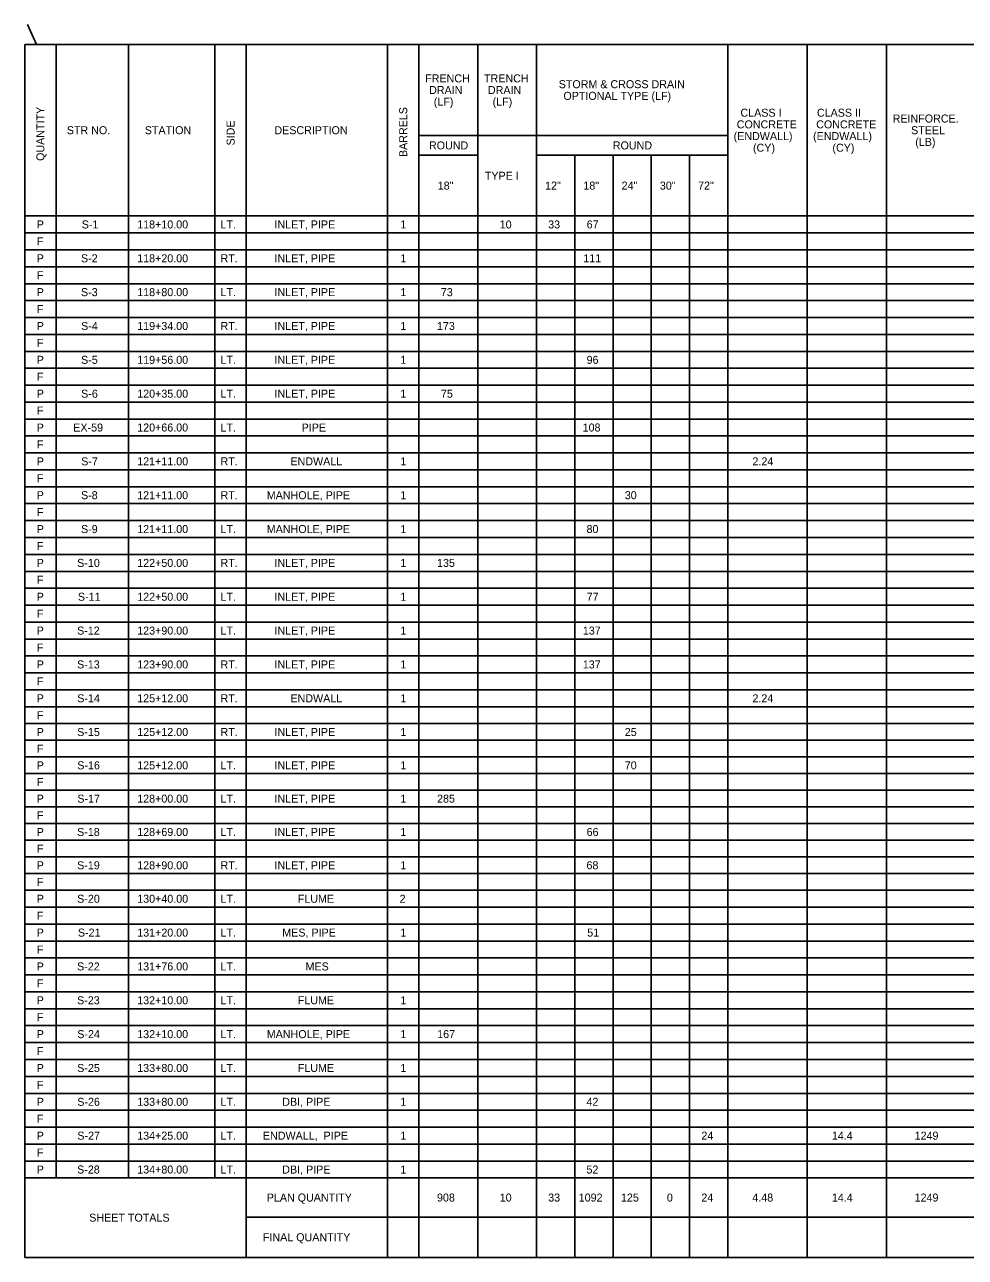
# Model space of a CAD drawing. Extents: x 0 to 765, y -1227 to 479.
# Drawn here: x 0.3 to 360, y 7 to 478.6 of the extents above; entities that cross this region are included whole.
import ezdxf

# ---------------------------------------------------------------- set-up
doc = ezdxf.new("R2010")
doc.units = 0
for name, color, linetype in [('Miscellaneous0', 7, 'Continuous'), ('PlotBorder_dp', 7, 'Continuous'), ('SheetLines_dp', 7, 'Continuous'), ('TextMinor', 7, 'Continuous'), ('TextShtNo', 7, 'Continuous')]:
    doc.layers.add(name, color=color, linetype=linetype)

msp = doc.modelspace()

# ---------------------------------------------------------------- linework, layer by layer
at = {"layer": 'PlotBorder_dp'}
for p, q in [((12.29, 471.05), (12.29, 37.35)), ((12.29, 471.05), (12.29, 37.35)), ((40.04, 471.05), (40.04, 37.35)), ((40.04, 471.05), (40.04, 37.35)), ((85.04, 471.05), (85.04, 6.97)), ((139.04, 471.05), (139.04, 6.97)), ((151.04, 471.05), (151.04, 6.97)), ((151.04, 471.05), (151.04, 6.97)), ((173.54, 471.05), (173.54, 6.97)), ((173.54, 471.05), (173.54, 6.97)), ((196.04, 471.05), (196.04, 6.97)), ((196.04, 471.05), (196.04, 6.97)), ((269.16, 471.05), (269.16, 6.97)), ((269.16, 471.05), (269.16, 6.97)), ((299.54, 471.05), (299.54, 405.42)), ((299.54, 471.05), (299.54, 6.97)), ((329.91, 471.05), (329.91, 405.42)), ((329.91, 471.05), (329.91, 6.97)), ((151.04, 436.17), (269.16, 436.17)), ((151.04, 428.67), (173.54, 428.67)), ((151.04, 428.67), (173.54, 428.67)), ((196.04, 428.67), (269.16, 428.67)), ((196.04, 428.67), (269.16, 428.67)), ((210.66, 428.67), (210.66, 6.97)), ((210.66, 428.67), (210.66, 6.97)), ((225.29, 428.67), (225.29, 6.97)), ((225.29, 428.67), (225.29, 6.97)), ((239.91, 428.67), (239.91, 6.97)), ((239.91, 428.67), (239.91, 6.97)), ((254.54, 428.67), (254.54, 22.35)), ((254.54, 428.67), (254.54, 6.97)), ((73.04, 405.42), (73.04, 37.35)), ((73.04, 405.42), (73.04, 37.35)), ((85.04, 405.42), (85.04, 6.97)), ((139.04, 405.42), (139.04, 398.95)), ((139.04, 147.42), (139.04, 6.97)), ((0.29, 37.35), (764.54, 37.35)), ((299.54, 37.35), (299.54, 6.97)), ((329.91, 37.35), (329.91, 6.97)), ((85.04, 22.35), (764.54, 22.35)), ((85.04, 22.35), (764.54, 22.35))]:
    msp.add_line(p, q, dxfattribs=at)
at = {"layer": 'SheetLines_dp'}
for p, q in [((0.29, 471.05), (764.54, 471.05)), ((0.29, 471.05), (0.29, 6.97)), ((73.04, 471.05), (73.04, 405.42)), ((0.29, 405.42), (764.54, 405.42)), ((0.29, 405.42), (764.54, 405.42)), ((0.29, 6.97), (764.54, 6.97))]:
    msp.add_line(p, q, dxfattribs=at)
at = {"layer": 'TextMinor'}
for p, q in [((0.29, 398.95), (764.54, 398.95)), ((40.04, 398.95), (85.04, 398.95)), ((0.29, 392.47), (764.54, 392.47)), ((0.29, 392.47), (764.54, 392.47)), ((0.29, 386), (764.54, 386)), ((12.29, 386), (764.54, 386)), ((0.29, 379.52), (764.54, 379.52)), ((0.29, 379.52), (764.54, 379.52)), ((0.29, 373.05), (764.54, 373.05)), ((12.29, 373.05), (764.54, 373.05)), ((0.29, 366.57), (764.54, 366.57)), ((0.29, 366.57), (764.54, 366.57)), ((0.29, 360.1), (764.54, 360.1)), ((12.29, 360.1), (764.54, 360.1)), ((0.29, 353.62), (764.54, 353.62)), ((0.29, 353.62), (764.54, 353.62)), ((0.29, 347.15), (764.54, 347.15)), ((12.29, 347.15), (764.54, 347.15)), ((0.29, 340.67), (764.54, 340.67)), ((0.29, 340.67), (764.54, 340.67)), ((0.29, 334.2), (764.54, 334.2)), ((12.29, 334.2), (764.54, 334.2)), ((0.29, 327.72), (764.54, 327.72)), ((0.29, 327.72), (764.54, 327.72)), ((0.29, 321.25), (764.54, 321.25)), ((12.29, 321.25), (764.54, 321.25)), ((0.29, 314.77), (764.54, 314.77)), ((0.29, 314.77), (764.54, 314.77)), ((0.29, 308.3), (764.54, 308.3)), ((12.29, 308.3), (764.54, 308.3)), ((0.29, 301.82), (764.54, 301.82)), ((0.29, 301.82), (764.54, 301.82)), ((0.29, 295.35), (764.54, 295.35)), ((12.29, 295.35), (764.54, 295.35)), ((0.29, 288.87), (764.54, 288.87)), ((0.29, 288.87), (764.54, 288.87)), ((0.29, 282.4), (764.54, 282.4)), ((12.29, 282.4), (764.54, 282.4)), ((0.29, 275.92), (764.54, 275.92)), ((0.29, 275.92), (764.54, 275.92)), ((0.29, 269.45), (764.54, 269.45)), ((12.29, 269.45), (764.54, 269.45)), ((0.29, 262.97), (764.54, 262.97)), ((0.29, 262.97), (764.54, 262.97)), ((0.29, 256.5), (764.54, 256.5)), ((12.29, 256.5), (764.54, 256.5)), ((0.29, 250.02), (764.54, 250.02)), ((0.29, 250.02), (764.54, 250.02)), ((0.29, 243.55), (764.54, 243.55)), ((12.29, 243.55), (764.54, 243.55)), ((0.29, 237.07), (764.54, 237.07)), ((0.29, 237.07), (764.54, 237.07)), ((0.29, 230.6), (764.54, 230.6)), ((12.29, 230.6), (764.54, 230.6)), ((0.29, 224.12), (764.54, 224.12)), ((0.29, 224.12), (764.54, 224.12)), ((0.29, 217.65), (764.54, 217.65)), ((12.29, 217.65), (764.54, 217.65)), ((0.29, 211.17), (764.54, 211.17)), ((0.29, 211.17), (764.54, 211.17)), ((0.29, 204.8), (764.54, 204.8)), ((12.29, 204.8), (764.54, 204.8)), ((0.29, 198.42), (764.54, 198.42)), ((0.29, 198.42), (764.54, 198.42)), ((0.29, 192.05), (764.54, 192.05)), ((12.29, 192.05), (764.54, 192.05)), ((0.29, 185.67), (764.54, 185.67)), ((0.29, 185.67), (764.54, 185.67)), ((0.29, 179.3), (764.54, 179.3)), ((12.29, 179.3), (764.54, 179.3)), ((0.29, 172.92), (764.54, 172.92)), ((0.29, 172.92), (764.54, 172.92)), ((0.29, 166.55), (764.54, 166.55)), ((12.29, 166.55), (764.54, 166.55)), ((0.29, 160.17), (764.54, 160.17)), ((0.29, 160.17), (764.54, 160.17)), ((0.29, 153.8), (764.54, 153.8)), ((12.29, 153.8), (764.54, 153.8)), ((0.29, 147.42), (764.54, 147.42)), ((0.29, 147.42), (764.54, 147.42)), ((0.29, 140.95), (764.54, 140.95)), ((0.29, 140.95), (764.54, 140.95)), ((0.29, 134.47), (764.54, 134.47)), ((0.29, 134.47), (764.54, 134.47)), ((0.29, 128), (764.54, 128)), ((0.29, 128), (764.54, 128)), ((0.29, 121.52), (764.54, 121.52)), ((0.29, 121.52), (764.54, 121.52)), ((0.29, 115.05), (764.54, 115.05)), ((0.29, 115.05), (764.54, 115.05)), ((0.29, 108.57), (764.54, 108.57)), ((0.29, 108.57), (764.54, 108.57)), ((0.29, 102.1), (764.54, 102.1)), ((0.29, 102.1), (764.54, 102.1)), ((0.29, 95.62), (764.54, 95.62)), ((0.29, 95.62), (764.54, 95.62)), ((0.29, 89.15), (764.54, 89.15)), ((0.29, 89.15), (764.54, 89.15)), ((0.29, 82.67), (764.54, 82.67)), ((0.29, 82.67), (764.54, 82.67)), ((0.29, 76.2), (764.54, 76.2)), ((0.29, 76.2), (764.54, 76.2)), ((0.29, 69.72), (764.54, 69.72)), ((0.29, 69.72), (764.54, 69.72)), ((0.29, 63.25), (764.54, 63.25)), ((0.29, 63.25), (764.54, 63.25)), ((0.29, 56.77), (764.54, 56.77)), ((0.29, 56.77), (764.54, 56.77)), ((0.29, 50.3), (764.54, 50.3)), ((0.29, 50.3), (764.54, 50.3)), ((0.29, 43.82), (764.54, 43.82)), ((0.29, 43.82), (764.54, 43.82)), ((0.29, 37.35), (764.54, 37.35))]:
    msp.add_line(p, q, dxfattribs=at)
at = {"layer": 'TextShtNo'}
msp.add_line((4.8, 471.05), (1.37, 478.62), dxfattribs=at)

# ---------------------------------------------------------------- texts
at = {"layer": 'Miscellaneous0'}
for s, height, p in [('FRENCH', 3.062, (153.45, 456.54)), ('TRENCH', 3.062, (175.95, 456.54)), ('DRAIN', 3.062, (154.94, 452.08)), ('DRAIN', 3.062, (177.44, 452.08)), ('STORM & CROSS DRAIN', 3.0625, (204.5, 454.31)), ('OPTIONAL TYPE (LF)', 3.0625, (206.3, 449.85)), ('(LF)', 3.062, (156.74, 447.62)), ('(LF)', 3.062, (179.24, 447.62)), (' CLASS I', 3.062, (272.87, 443.4)), ('CLASS II', 3.062, (303.25, 443.4)), ('REINFORCE.', 3.062, (332.2, 441.17)), ('STR NO.', 3.062, (16.4, 436.7)), ('STATION', 3.062, (46.22, 436.7)), ('DESCRIPTION', 3.0625, (95.79, 436.7)), ('CONCRETE', 3.062, (272.59, 438.94)), ('CONCRETE', 3.062, (302.97, 438.94)), ('STEEL', 3.062, (339.25, 436.7)), ('ROUND', 3.062, (154.89, 430.89)), ('ROUND', 3.062, (225.2, 430.89)), ('(ENDWALL)', 3.062, (271.39, 434.47)), ('(ENDWALL)', 3.062, (301.77, 434.47)), ('(LB)', 3.062, (340.86, 432.24)), ('(CY)', 3.062, (278.8, 430.01)), ('(CY)', 3.062, (309.18, 430.01)), ('TYPE I', 3.062, (176.27, 419.27)), ('18"', 3.062, (158.25, 415.52)), ('12"', 3.062, (199.31, 415.52)), ('18"', 3.062, (213.94, 415.52)), ('24"', 3.062, (228.56, 415.52)), ('30"', 3.062, (243.19, 415.52)), ('72"', 3.062, (257.81, 415.52)), ('P', 3.06, (4.9, 400.65)), ('S-1', 3.062, (22.12, 400.65)), ('118+10.00', 3.062, (43.33, 400.65)), ('LT.', 3.062, (75.2, 400.65)), ('INLET, PIPE', 3.0625, (95.83, 400.65)), ('1', 3.06, (143.96, 400.65)), ('10', 3.062, (181.96, 400.65)), ('33', 3.062, (200.49, 400.65)), ('67', 3.062, (215.21, 400.65)), ('F', 3.06, (4.95, 394.18)), ('P', 3.06, (4.9, 387.7)), ('S-2', 3.062, (21.83, 387.7)), ('118+20.00', 3.062, (43.33, 387.7)), ('RT.', 3.062, (75.2, 387.7)), ('INLET, PIPE', 3.0625, (95.83, 387.7)), ('1', 3.06, (143.96, 387.7)), ('111', 3.062, (213.93, 387.7)), ('F', 3.06, (4.95, 381.23)), ('P', 3.06, (4.9, 374.75)), ('S-3', 3.062, (21.83, 374.75)), ('118+80.00', 3.062, (43.33, 374.75)), ('LT.', 3.062, (75.2, 374.75)), ('INLET, PIPE', 3.0625, (95.83, 374.75)), ('1', 3.06, (143.96, 374.75)), ('73', 3.062, (159.43, 374.75)), ('F', 3.06, (4.95, 368.28)), ('P', 3.06, (4.9, 361.8)), ('S-4', 3.062, (21.89, 361.8)), ('119+34.00', 3.062, (43.33, 361.8)), ('RT.', 3.062, (75.2, 361.8)), ('INLET, PIPE', 3.0625, (95.83, 361.8)), ('1', 3.06, (143.96, 361.8)), ('173', 3.062, (157.95, 361.8)), ('F', 3.06, (4.95, 355.33)), ('P', 3.06, (4.9, 348.85)), ('S-5', 3.062, (21.86, 348.85)), ('119+56.00', 3.062, (43.33, 348.85)), ('LT.', 3.062, (75.2, 348.85)), ('INLET, PIPE', 3.0625, (95.83, 348.85)), ('1', 3.06, (143.96, 348.85)), ('96', 3.062, (215.18, 348.85)), ('F', 3.06, (4.95, 342.38)), ('P', 3.06, (4.9, 335.9)), ('S-6', 3.062, (21.89, 335.9)), ('120+35.00', 3.062, (43.33, 335.9)), ('LT.', 3.062, (75.2, 335.9)), ('INLET, PIPE', 3.0625, (95.83, 335.9)), ('1', 3.06, (143.96, 335.9)), ('75', 3.062, (159.47, 335.9)), ('F', 3.06, (4.95, 329.43)), ('P', 3.06, (4.9, 322.95)), ('EX-59', 3.062, (18.88, 322.95)), ('120+66.00', 3.062, (43.33, 322.95)), ('LT.', 3.062, (75.2, 322.95)), ('PIPE', 3.062, (106.21, 322.95)), ('108', 3.062, (213.65, 322.95)), ('F', 3.06, (4.95, 316.48)), ('P', 3.06, (4.9, 310)), ('S-7', 3.062, (21.91, 310)), ('121+11.00', 3.062, (43.33, 310)), ('RT.', 3.062, (75.2, 310)), ('ENDWALL', 3.062, (101.92, 310)), ('1', 3.06, (143.96, 310)), ('2.24', 3.062, (278.59, 310)), ('F', 3.06, (4.95, 303.53)), ('P', 3.06, (4.9, 297.05)), ('S-8', 3.062, (21.84, 297.05)), ('121+11.00', 3.062, (43.33, 297.05)), ('RT.', 3.062, (75.2, 297.05)), ('MANHOLE, PIPE', 3.0625, (92.87, 297.05)), ('1', 3.06, (143.96, 297.05)), ('30', 3.062, (229.77, 297.05)), ('F', 3.06, (4.95, 290.58)), ('P', 3.06, (4.9, 284.1)), ('S-9', 3.062, (21.84, 284.1)), ('121+11.00', 3.062, (43.33, 284.1)), ('LT.', 3.062, (75.2, 284.1)), ('MANHOLE, PIPE', 3.0625, (92.87, 284.1)), ('1', 3.06, (143.96, 284.1)), ('80', 3.062, (215.15, 284.1)), ('F', 3.06, (4.95, 277.63)), ('P', 3.06, (4.9, 271.15)), ('S-10', 3.062, (20.37, 271.15)), ('122+50.00', 3.062, (43.33, 271.15)), ('RT.', 3.062, (75.2, 271.15)), ('INLET, PIPE', 3.0625, (95.83, 271.15)), ('1', 3.06, (143.96, 271.15)), ('135', 3.062, (157.99, 271.15)), ('F', 3.06, (4.95, 264.68)), ('P', 3.06, (4.9, 258.2)), ('S-11', 3.062, (20.64, 258.2)), ('122+50.00', 3.062, (43.33, 258.2)), ('LT.', 3.062, (75.2, 258.2)), ('INLET, PIPE', 3.0625, (95.83, 258.2)), ('1', 3.06, (143.96, 258.2)), ('77', 3.062, (215.21, 258.2)), ('F', 3.06, (4.95, 251.73)), ('P', 3.06, (4.9, 245.25)), ('S-12', 3.062, (20.34, 245.25)), ('123+90.00', 3.062, (43.33, 245.25)), ('LT.', 3.062, (75.2, 245.25)), ('INLET, PIPE', 3.0625, (95.83, 245.25)), ('1', 3.06, (143.96, 245.25)), ('137', 3.062, (213.73, 245.25)), ('F', 3.06, (4.95, 238.78)), ('P', 3.06, (4.9, 232.3)), ('S-13', 3.062, (20.34, 232.3)), ('123+90.00', 3.062, (43.33, 232.3)), ('RT.', 3.062, (75.2, 232.3)), ('INLET, PIPE', 3.0625, (95.83, 232.3)), ('1', 3.06, (143.96, 232.3)), ('137', 3.062, (213.73, 232.3)), ('F', 3.06, (4.95, 225.83)), ('P', 3.06, (4.9, 219.35)), ('S-14', 3.062, (20.4, 219.35)), ('125+12.00', 3.062, (43.33, 219.35)), ('RT.', 3.062, (75.2, 219.35)), ('ENDWALL', 3.062, (101.92, 219.35)), ('1', 3.06, (143.96, 219.35)), ('2.24', 3.062, (278.59, 219.35)), ('F', 3.06, (4.95, 212.88)), ('P', 3.06, (4.9, 206.45)), ('S-15', 3.062, (20.38, 206.45)), ('125+12.00', 3.062, (43.33, 206.45)), ('RT.', 3.062, (75.2, 206.45)), ('INLET, PIPE', 3.0625, (95.83, 206.45)), ('1', 3.06, (143.96, 206.45)), ('25', 3.062, (229.78, 206.45)), ('F', 3.06, (4.95, 200.08)), ('P', 3.06, (4.9, 193.7)), ('S-16', 3.062, (20.41, 193.7)), ('125+12.00', 3.062, (43.33, 193.7)), ('LT.', 3.062, (75.2, 193.7)), ('INLET, PIPE', 3.0625, (95.83, 193.7)), ('1', 3.06, (143.96, 193.7)), ('70', 3.062, (229.77, 193.7)), ('F', 3.06, (4.95, 187.33)), ('P', 3.06, (4.9, 180.95)), ('S-17', 3.062, (20.43, 180.95)), ('128+00.00', 3.062, (43.33, 180.95)), ('LT.', 3.062, (75.2, 180.95)), ('INLET, PIPE', 3.0625, (95.83, 180.95)), ('1', 3.06, (143.96, 180.95)), ('285', 3.062, (157.99, 180.95)), ('F', 3.06, (4.95, 174.58)), ('P', 3.06, (4.9, 168.2)), ('S-18', 3.062, (20.35, 168.2)), ('128+69.00', 3.062, (43.33, 168.2)), ('LT.', 3.062, (75.2, 168.2)), ('INLET, PIPE', 3.0625, (95.83, 168.2)), ('1', 3.06, (143.96, 168.2)), ('66', 3.062, (215.18, 168.2)), ('F', 3.06, (4.95, 161.83)), ('P', 3.06, (4.9, 155.45)), ('S-19', 3.062, (20.36, 155.45)), ('128+90.00', 3.062, (43.33, 155.45)), ('RT.', 3.062, (75.2, 155.45)), ('INLET, PIPE', 3.0625, (95.83, 155.45)), ('1', 3.06, (143.96, 155.45)), ('68', 3.062, (215.13, 155.45)), ('F', 3.06, (4.95, 149.08)), ('P', 3.06, (4.9, 142.65)), ('S-20', 3.062, (20.37, 142.65)), ('130+40.00', 3.062, (43.33, 142.65)), ('LT.', 3.062, (75.2, 142.65)), ('FLUME', 3.062, (104.73, 142.65)), ('2', 3.06, (143.67, 142.65)), ('F', 3.06, (4.95, 136.18)), ('P', 3.06, (4.9, 129.7)), ('S-21', 3.062, (20.64, 129.7)), ('131+20.00', 3.062, (43.33, 129.7)), ('LT.', 3.062, (75.2, 129.7)), ('MES, PIPE', 3.062, (98.8, 129.7)), ('1', 3.06, (143.96, 129.7)), ('51', 3.062, (215.42, 129.7)), ('F', 3.06, (4.95, 123.23)), ('P', 3.06, (4.9, 116.75)), ('S-22', 3.062, (20.34, 116.75)), ('131+76.00', 3.062, (43.33, 116.75)), ('LT.', 3.062, (75.2, 116.75)), ('MES', 3.062, (107.7, 116.75)), ('F', 3.06, (4.95, 110.28)), ('P', 3.06, (4.9, 103.8)), ('S-23', 3.062, (20.34, 103.8)), ('132+10.00', 3.062, (43.33, 103.8)), ('LT.', 3.062, (75.2, 103.8)), ('FLUME', 3.062, (104.73, 103.8)), ('1', 3.06, (143.96, 103.8)), ('F', 3.06, (4.95, 97.33)), ('P', 3.06, (4.9, 90.85)), ('S-24', 3.062, (20.4, 90.85)), ('132+10.00', 3.062, (43.33, 90.85)), ('LT.', 3.062, (75.2, 90.85)), ('MANHOLE, PIPE', 3.0625, (92.87, 90.85)), ('1', 3.06, (143.96, 90.85)), ('167', 3.062, (158.04, 90.85)), ('F', 3.06, (4.95, 84.38)), ('P', 3.06, (4.9, 77.9)), ('S-25', 3.062, (20.38, 77.9)), ('133+80.00', 3.062, (43.33, 77.9)), ('LT.', 3.062, (75.2, 77.9)), ('FLUME', 3.062, (104.73, 77.9)), ('1', 3.06, (143.96, 77.9)), ('F', 3.06, (4.95, 71.43)), ('P', 3.06, (4.9, 64.95)), ('S-26', 3.062, (20.41, 64.95)), ('133+80.00', 3.062, (43.33, 64.95)), ('LT.', 3.062, (75.2, 64.95)), ('DBI, PIPE', 3.062, (98.8, 64.95)), ('1', 3.06, (143.96, 64.95)), ('42', 3.062, (215.12, 64.95)), ('F', 3.06, (4.95, 58.48)), ('P', 3.06, (4.9, 52)), ('S-27', 3.062, (20.43, 52)), ('134+25.00', 3.062, (43.33, 52)), ('LT.', 3.062, (75.2, 52)), ('ENDWALL,  PIPE', 3.0625, (91.39, 52)), ('1', 3.06, (143.96, 52)), ('24', 3.062, (259.06, 52)), ('14.4', 3.062, (308.97, 52)), ('1249', 3.062, (340.61, 52)), ('F', 3.06, (4.95, 45.53)), ('P', 3.06, (4.9, 39.05)), ('S-28', 3.062, (20.35, 39.05)), ('134+80.00', 3.062, (43.33, 39.05)), ('LT.', 3.062, (75.2, 39.05)), ('DBI, PIPE', 3.062, (98.8, 39.05)), ('1', 3.06, (143.96, 39.05)), ('52', 3.062, (215.12, 39.05)), ('PLAN QUANTITY', 3.0625, (92.87, 28.32)), ('908', 3.062, (157.96, 28.32)), ('10', 3.062, (181.96, 28.32)), ('33', 3.062, (200.49, 28.32)), ('1092', 3.062, (212.16, 28.32)), ('125', 3.062, (228.3, 28.32)), ('0', 3.06, (245.88, 28.32)), ('24', 3.062, (259.06, 28.32)), ('4.48', 3.062, (278.54, 28.32)), ('14.4', 3.062, (308.97, 28.32)), ('1249', 3.062, (340.61, 28.32)), ('SHEET TOTALS', 3.0625, (24.98, 20.63)), ('FINAL QUANTITY', 3.0625, (91.39, 13.13))]:
    msp.add_text(s, height=height, dxfattribs=at).set_placement(p)
for s, p in [('QUANTITY', (7.82, 426.48)), ('BARRELS', (146.57, 427.97)), ('SIDE', (80.57, 432.4))]:
    msp.add_text(s, height=3.062, rotation=90, dxfattribs=at).set_placement(p)

doc.saveas('drawing.dxf')
